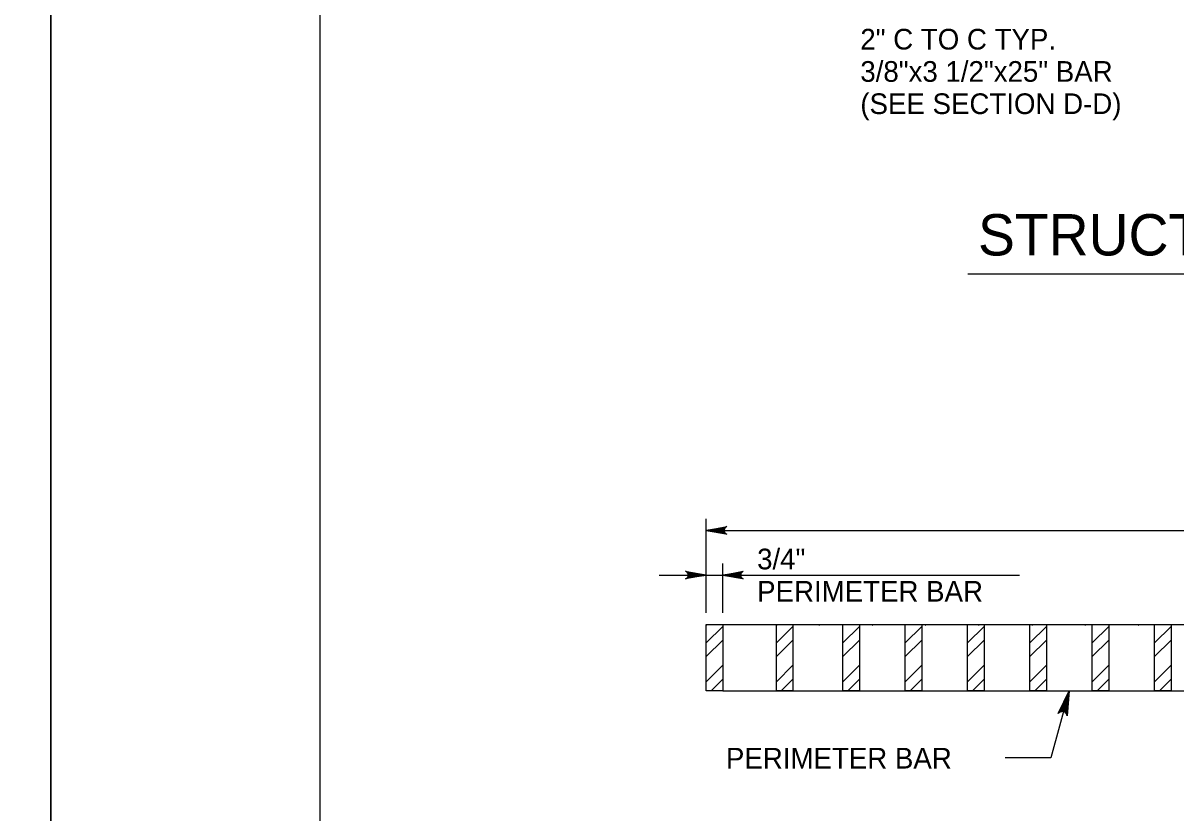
# Model space of a CAD drawing. Extents: x 2087776 to 2104538, y 970919 to 982612.
# Drawn here: x 2098799 to 2099348, y 979638 to 980014 of the extents above; entities that cross this region are included whole.
import ezdxf

# ---------------------------------------------------------------- set-up
doc = ezdxf.new("R2010")
doc.units = 0
doc.layers.add('1', color=7, linetype='Continuous')
doc.layers.add('PLT-BNDY', color=7, linetype='Continuous')

msp = doc.modelspace()

# ---------------------------------------------------------------- linework, layer by layer
at = {"layer": '1'}
for p, q in [((2099248.82, 979894.84), (2099679.88, 979894.84)), ((2099124.34, 979733.43), (2099124.34, 979778.25)), ((2099124.34, 979772.74), (2099824.11, 979772.74)), ((2099124.34, 979733.43), (2099124.34, 979756.96)), ((2099132.22, 979733.43), (2099132.22, 979756.96)), ((2099102.03, 979751.44), (2099273.41, 979751.44)), ((2099124.34, 979696.42), (2099124.34, 979727.91)), ((2099132.22, 979727.91), (2099824.11, 979727.91)), ((2099157.75, 979696.42), (2099157.75, 979727.91)), ((2099189.39, 979696.42), (2099189.39, 979727.91)), ((2099219.06, 979696.42), (2099219.06, 979727.91)), ((2099248.73, 979696.42), (2099248.73, 979727.91)), ((2099278.41, 979696.42), (2099278.41, 979727.91)), ((2099308.08, 979696.42), (2099308.08, 979727.91)), ((2099337.75, 979696.42), (2099337.75, 979727.91)), ((2099132.22, 979696.42), (2099824.11, 979696.42)), ((2099297.13, 979696.42), (2099288.36, 979664.46))]:
    msp.add_line(p, q, dxfattribs=at)
for points in [[(2101519.11, 978763.82), (2101519.11, 980614.22), (2098940.37, 980614.22), (2098940.37, 978763.82), (2101519.11, 978763.82), (2101519.11, 978850.3), (2100862.94, 978850.3), (2100862.94, 979062.5), (2101519.11, 979062.5), (2101519.11, 979157.53), (2100862.94, 979157.53), (2100862.94, 978763.82), (2101121.48, 978763.82), (2101121.48, 978850.3), (2101121.48, 978763.82), (2101374.1, 978763.82), (2101374.1, 978850.3), (2101374.1, 978809.9), (2101519.11, 978809.9)], [(2099124.34, 979772.74), (2099134.13, 979774.57), (2099133.75, 979774.31), (2099133.38, 979774.05), (2099133.18, 979773.72), (2099132.99, 979773.39), (2099132.93, 979773.07), (2099132.87, 979772.74), (2099132.93, 979772.41), (2099132.99, 979772.08), (2099133.18, 979771.75), (2099133.38, 979771.43), (2099133.75, 979771.16), (2099134.13, 979770.9), (2099124.34, 979772.74), (2099133.75, 979771.16), (2099133.38, 979771.43), (2099124.34, 979772.74), (2099133.18, 979771.75), (2099132.99, 979772.08), (2099124.34, 979772.74), (2099132.93, 979772.41), (2099132.87, 979772.74), (2099124.34, 979772.74), (2099132.93, 979773.07), (2099132.99, 979773.39), (2099124.34, 979772.74), (2099133.18, 979773.72), (2099133.38, 979774.05), (2099124.34, 979772.74), (2099133.75, 979774.31)], [(2099124.34, 979751.44), (2099114.56, 979749.61), (2099114.94, 979749.87), (2099115.31, 979750.13), (2099115.51, 979750.46), (2099115.7, 979750.79), (2099115.76, 979751.12), (2099115.81, 979751.44), (2099115.76, 979751.77), (2099115.7, 979752.1), (2099115.51, 979752.43), (2099115.31, 979752.76), (2099114.94, 979753.02), (2099114.56, 979753.28), (2099124.34, 979751.44), (2099114.94, 979753.02), (2099115.31, 979752.76), (2099124.34, 979751.44), (2099115.51, 979752.43), (2099115.7, 979752.1), (2099124.34, 979751.44), (2099115.76, 979751.77), (2099115.81, 979751.44), (2099124.34, 979751.44), (2099115.76, 979751.12), (2099115.7, 979750.79), (2099124.34, 979751.44), (2099115.51, 979750.46), (2099115.31, 979750.13), (2099124.34, 979751.44), (2099114.94, 979749.87)], [(2099132.22, 979751.44), (2099142, 979753.28), (2099141.63, 979753.02), (2099141.25, 979752.76), (2099141.06, 979752.43), (2099140.86, 979752.1), (2099140.8, 979751.77), (2099140.75, 979751.44), (2099140.8, 979751.12), (2099140.86, 979750.79), (2099141.06, 979750.46), (2099141.25, 979750.13), (2099141.63, 979749.87), (2099142, 979749.61), (2099132.22, 979751.44), (2099141.63, 979749.87), (2099141.25, 979750.13), (2099132.22, 979751.44), (2099141.06, 979750.46), (2099140.86, 979750.79), (2099132.22, 979751.44), (2099140.8, 979751.12), (2099140.75, 979751.44), (2099132.22, 979751.44), (2099140.8, 979751.77), (2099140.86, 979752.1), (2099132.22, 979751.44), (2099141.06, 979752.43), (2099141.25, 979752.76), (2099132.22, 979751.44), (2099141.63, 979753.02)], [(2099124.34, 979727.52), (2099124.74, 979727.91)], [(2099124.34, 979719.17), (2099132.22, 979727.04)], [(2099157.75, 979727.52), (2099158.14, 979727.91)], [(2099157.75, 979719.17), (2099165.62, 979727.04)], [(2099177.97, 979727.52), (2099178.36, 979727.91)], [(2099189.39, 979719.17), (2099197.26, 979727.04)], [(2099203.3, 979727.52), (2099203.69, 979727.91)], [(2099219.06, 979719.17), (2099226.94, 979727.04)], [(2099228.63, 979727.52), (2099229.02, 979727.91)], [(2099248.73, 979719.17), (2099256.61, 979727.04)], [(2099253.96, 979727.52), (2099254.36, 979727.91)], [(2099278.41, 979719.17), (2099286.28, 979727.04)], [(2099279.3, 979727.52), (2099279.69, 979727.91)], [(2099304.63, 979727.52), (2099305.03, 979727.91)], [(2099308.08, 979719.17), (2099315.95, 979727.04)], [(2099329.97, 979727.52), (2099330.36, 979727.91)], [(2099337.75, 979719.17), (2099345.62, 979727.04)], [(2099124.34, 979712.68), (2099132.22, 979720.55)], [(2099157.75, 979712.68), (2099165.62, 979720.55)], [(2099189.39, 979712.68), (2099197.26, 979720.55)], [(2099219.06, 979712.68), (2099226.94, 979720.55)], [(2099248.73, 979712.68), (2099256.61, 979720.55)], [(2099278.41, 979712.68), (2099286.28, 979720.55)], [(2099308.08, 979712.68), (2099315.95, 979720.55)], [(2099337.75, 979712.68), (2099345.62, 979720.55)], [(2099124.34, 979700.69), (2099132.22, 979708.56)], [(2099157.75, 979700.69), (2099165.62, 979708.56)], [(2099189.39, 979700.69), (2099197.26, 979708.56)], [(2099219.06, 979700.69), (2099226.94, 979708.56)], [(2099248.73, 979700.69), (2099256.61, 979708.56)], [(2099278.41, 979700.69), (2099286.28, 979708.56)], [(2099308.08, 979700.69), (2099315.95, 979708.56)], [(2099337.75, 979700.69), (2099345.62, 979708.56)], [(2099126.65, 979696.42), (2099132.22, 979701.99)], [(2099160.05, 979696.42), (2099165.62, 979701.99)], [(2099191.69, 979696.42), (2099197.26, 979701.99)], [(2099221.37, 979696.42), (2099226.94, 979701.99)], [(2099251.04, 979696.42), (2099256.61, 979701.99)], [(2099280.71, 979696.42), (2099286.28, 979701.99)], [(2099310.38, 979696.42), (2099315.95, 979701.99)], [(2099340.05, 979696.42), (2099345.62, 979701.99)], [(2099297.13, 979696.42), (2099296.21, 979684.44), (2099296.03, 979684.96), (2099295.84, 979685.48), (2099295.52, 979685.81), (2099295.2, 979686.14), (2099294.83, 979686.31), (2099294.47, 979686.47), (2099294.07, 979686.51), (2099293.67, 979686.55), (2099293.22, 979686.42), (2099292.78, 979686.3), (2099292.36, 979685.94), (2099291.94, 979685.58), (2099297.13, 979696.42), (2099292.36, 979685.94), (2099292.78, 979686.3), (2099297.13, 979696.42), (2099293.22, 979686.42), (2099293.67, 979686.55), (2099297.13, 979696.42), (2099294.07, 979686.51), (2099294.47, 979686.47), (2099297.13, 979696.42), (2099294.83, 979686.31), (2099295.2, 979686.14), (2099297.13, 979696.42), (2099295.52, 979685.81), (2099295.84, 979685.48), (2099297.13, 979696.42), (2099296.03, 979684.96)], [(2099288.36, 979664.46), (2099266.59, 979664.46)]]:
    msp.add_lwpolyline(points, dxfattribs=at)
for points in [[(2099124.34, 979696.42), (2099124.34, 979727.91), (2099132.22, 979727.91), (2099132.22, 979696.42)], [(2099157.75, 979696.42), (2099157.75, 979727.91), (2099165.62, 979727.91), (2099165.62, 979696.42)], [(2099189.39, 979696.42), (2099189.39, 979727.91), (2099197.26, 979727.91), (2099197.26, 979696.42)], [(2099219.06, 979696.42), (2099219.06, 979727.91), (2099226.94, 979727.91), (2099226.94, 979696.42)], [(2099248.73, 979696.42), (2099248.73, 979727.91), (2099256.61, 979727.91), (2099256.61, 979696.42)], [(2099278.41, 979696.42), (2099278.41, 979727.91), (2099286.28, 979727.91), (2099286.28, 979696.42)], [(2099308.08, 979696.42), (2099308.08, 979727.91), (2099315.95, 979727.91), (2099315.95, 979696.42)], [(2099337.75, 979696.42), (2099337.75, 979727.91), (2099345.62, 979727.91), (2099345.62, 979696.42)]]:
    msp.add_lwpolyline(points, close=True, dxfattribs=at)
at = {"layer": 'PLT-BNDY'}
for points in [[(2096053.23, 980663.43), (2098812.42, 980663.43), (2098812.42, 978714.61), (2096053.23, 978714.61)], [(2098812.42, 980663.43), (2101571.61, 980663.43), (2101571.61, 978714.61), (2098812.42, 978714.61)]]:
    msp.add_lwpolyline(points, close=True, dxfattribs=at)

# ---------------------------------------------------------------- texts
at = {"layer": '1'}
for s, height, p in [('2" C TO C TYP.', 9.8425, (2099197.71, 980001.61)), ('3/8"x3 1/2"x25" BAR', 9.8425, (2099197.71, 979986.26)), ('(SEE SECTION D-D)', 9.8425, (2099197.71, 979970.9)), ('STRUCTURAL STEEL GRATE', 19.685, (2099253.73, 979903.59)), ('3/4"', 9.843, (2099148.58, 979754.19)), ('PERIMETER BAR', 9.8425, (2099148.58, 979738.83)), ('PERIMETER BAR', 9.8425, (2099133.73, 979659.38))]:
    msp.add_text(s, height=height, dxfattribs=at).set_placement(p)

doc.saveas('drawing.dxf')
